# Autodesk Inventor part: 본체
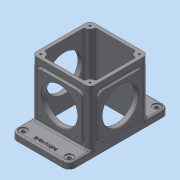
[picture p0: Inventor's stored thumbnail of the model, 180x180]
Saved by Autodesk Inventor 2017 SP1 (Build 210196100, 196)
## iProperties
Created: 2018-09
Part Number: 본체
Material: 알루미늄 6061
Document SubType Name: Modeling
Designer: mduedu
Density: 2.71 g/cm^3
Mass: 972.977 g
Surface Area: 957.184 cm^2
Volume: 359.032 cm^3
Appearance: 기본값
Author: mduedu
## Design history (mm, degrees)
sketch "스케치1"
  geometry: L1 (90, 52.5)-(-90, 52.5); L2 (-90, 52.5)-(-90, -52.5); L3 (-90, -52.5)-(90, -52.5); L4 (90, -52.5)-(90, 52.5); L5 (90, 52.5)-(-90, -52.5); L6 (-90, 52.5)-(90, -52.5); 1 further point
  constraints: 12 end point, 2 midpoint, 2 parallel, 1 horizontal, 1 perpendicular
  dimensions: "d0" = 180 distance of L3.end L2.end; "d1" = 105 distance of L2.end L1.end
extrude "돌출1" new body sketch "스케치1" distance "d2" = 12; taper "d3" = 0 deg
sketch "스케치2"
  geometry: L1 (-52.5, -52.5)-(52.5, -52.5); L2 (52.5, -52.5)-(52.5, 52.5); L3 (52.5, 52.5)-(-52.5, 52.5); L4 (-52.5, 52.5)-(-52.5, -52.5); L5 (-52.5, -52.5)-(52.5, 52.5); L6 (52.5, -52.5)-(-52.5, 52.5); 1 further point
  constraints: 12 end point, 2 midpoint, 2 parallel, 1 horizontal, 1 perpendicular
  dimensions: "d4" = 105 distance of L3.end L2.end; "d5" = 105 distance of L2.end L1.end
extrude "돌출2" join sketch "스케치2" distance "d6" = 100; taper "d7" = 0 deg
sketch "스케치14"
  geometry: L1 (-52.5, 52.5)-(52.5, 52.5) reference; L2 (52.5, 52.5)-(52.5, -52.5) reference; L3 (52.5, -52.5)-(-52.5, -52.5) reference; L4 (-52.5, -52.5)-(-52.5, 52.5) reference; L5 (46.5, 46.5)-(-46.5, 46.5); L6 (-46.5, 46.5)-(-46.5, -46.5); L7 (-46.5, -46.5)-(46.5, -46.5); L8 (46.5, -46.5)-(46.5, 46.5); 1 further point
  constraints: 8 end point, 3 other
  dimensions: "d85" = 6 distance between parallel lines of L5 L1
extrude "돌출10" cut sketch "스케치14" stored distance "d86" = 10; taper "d87" = 0 deg
fillet "모깎기1" dims "d12" = 8
sketch "스케치15"
  geometry: A1 r 8 centre (-44.5, 44.5) between (-44.5, 52.5) and (-52.5, 44.5) reference; A2 r 8 centre (44.5, 44.5) between (52.5, 44.5) and (44.5, 52.5) reference; A3 r 8 centre (44.5, -44.5) between (44.5, -52.5) and (52.5, -44.5) reference; A4 r 8 centre (-44.5, -44.5) between (-52.5, -44.5) and (-44.5, -52.5) reference; 5 further points
  constraints: 4 coincident, 4 vertical alignment, 8 other
extrude "돌출11" join sketch "스케치15" stored distance "d88" = 10; taper "d89" = 0 deg
fillet "모깎기15" dims "d90" = 3
sketch "스케치6"
  geometry: L1 (50, 19)-(130, 19); L2 (130, 19)-(130, 99); L3 (130, 99)-(50, 99); L4 (50, 99)-(50, 19); L5 (50, 19)-(130, 99); L6 (130, 19)-(50, 99); L7 (0, 0)-(180, 0) reference; 4 further points
  constraints: 12 end point, 4 midpoint, 2 parallel, 1 horizontal, 1 perpendicular, 1 vertical alignment
  dimensions: "d25" = 80 distance of L3.end L2.end; "d26" = 80 distance of L2.end L1.end; "d27" = 59 distance of point (90, 0) point (90, 59)
extrude "돌출6" join sketch "스케치6" distance "d28" = 3; taper "d29" = 0 deg
fillet "모깎기7" dims "d30" = 8
sketch "스케치7"
  geometry: C1 r 32.5 at (90, 59); 1 further point
  constraints: 1 centre point, 1 vertical alignment
  dimensions: "d32" = 65 diameter of C1; "d33" = 59 distance of C1.centre point (90, 0)
extrude "돌출7" cut sketch "스케치7" stored distance "d34" = 3; taper "d35" = 0 deg
fillet "모깎기9" dims "d36" = 3
sketch "스케치8"
  geometry: L1 (4.5, 7)-(84.5, 7); L2 (84.5, 7)-(84.5, 87); L3 (84.5, 87)-(4.5, 87); L4 (4.5, 87)-(4.5, 7); L5 (4.5, 7)-(84.5, 87); L6 (84.5, 7)-(4.5, 87); L7 (-8, -12)-(97, -12) reference; C1 r 32.5 at (44.5, 47); 4 further points
  constraints: 12 end point, 4 midpoint, 2 parallel, 1 centre point, 1 coincident, 1 horizontal, 1 perpendicular, 1 vertical alignment
  dimensions: "d37" = 80 distance of L3.end L2.end; "d38" = 80 distance of L2.end L1.end; "d39" = 59 distance from line of point (44.5, 47) L7; "d40" = 65 diameter of C1
extrude "돌출8" join sketch "스케치8" distance "d41" = 3; taper "d42" = 0 deg
fillet "모깎기10" dims "d43" = 8
extrude "돌출9" cut sketch "스케치8" stored distance "d44" = 3; taper "d45" = 0 deg
fillet "모깎기11" dims "d46" = 3
sketch "스케치9"
  geometry: L1 (50, 91)-(50, 27) reference; L2 (58, 19)-(122, 19) reference; L3 (130, 27)-(130, 91) reference; L4 (122, 99)-(58, 99) reference; C1 r 32.5 at (90, 59) reference; A1 r 8 centre (58, 91) between (58, 99) and (50, 91) reference; A2 r 8 centre (58, 27) between (50, 27) and (58, 19) reference; A3 r 8 centre (122, 27) between (122, 19) and (130, 27) reference; A4 r 8 centre (122, 91) between (130, 91) and (122, 99) reference; 5 further points
  constraints: 4 coincident
hole "구멍1" sketch "스케치9" at (58, 91), (122, 91), (122, 27), (58, 27) diameter "d47" = 3.242; stored, may be unused: countersink angle "d51" = 90 deg, drill point angle "d53" = 118 deg; dims "d48" = 6, "d49" = 4, "d50" = 2, "d52" = 9
sketch "스케치10"
  geometry: L1 (12.5, 7)-(76.5, 7) reference; L2 (84.5, 15)-(84.5, 79) reference; L3 (76.5, 87)-(12.5, 87) reference; L4 (4.5, 79)-(4.5, 15) reference; C1 r 32.5 at (44.5, 47) reference; A1 r 8 centre (12.5, 15) between (4.5, 15) and (12.5, 7) reference; A2 r 8 centre (76.5, 15) between (76.5, 7) and (84.5, 15) reference; A3 r 8 centre (76.5, 79) between (84.5, 79) and (76.5, 87) reference; A4 r 8 centre (12.5, 79) between (12.5, 87) and (4.5, 79) reference; 5 further points
  constraints: 4 coincident
hole "구멍2" sketch "스케치10" at (12.5, 79), (76.5, 79), (76.5, 15), (12.5, 15) diameter "d54" = 3.242; stored, may be unused: countersink angle "d58" = 90 deg, drill point angle "d60" = 118 deg; dims "d55" = 6, "d56" = 4, "d57" = 2, "d59" = 9
fillet "모깎기12" dims "d68" = 11
sketch "스케치16"
  geometry: A1 r 11 centre (-79, 41.5) between (-79, 52.5) and (-90, 41.5) reference; A2 r 11 centre (-79, -41.5) between (-90, -41.5) and (-79, -52.5) reference; A3 r 11 centre (79, 41.5) between (90, 41.5) and (79, 52.5) reference; A4 r 11 centre (79, -41.5) between (79, -52.5) and (90, -41.5) reference; 5 further points
  constraints: 4 coincident
hole "구멍5" sketch "스케치16" at (-79, 41.5), (79, 41.5), (79, -41.5), (-79, -41.5) diameter "d91" = 6.6; stored, may be unused: countersink angle "d95" = 90 deg, drill point angle "d97" = 118 deg; dims "d92" = 6, "d93" = 14, "d94" = 2, "d96" = 8
fillet "모깎기13" dims "d77" = 3
fillet "모깎기14" dims "d78" = 3
chamfer "모따기1" distance "d79" = 1; stored, may be unused: second distance "d80" = 2, angle "d81" = 45 deg
sketch "스케치17"
  geometry: A1 r 8 centre (-44.5, 44.5) between (-44.5, 52.5) and (-52.5, 44.5) reference; A2 r 8 centre (-44.5, -44.5) between (-52.5, -44.5) and (-44.5, -52.5) reference; A3 r 8 centre (44.5, -44.5) between (44.5, -52.5) and (52.5, -44.5) reference; A4 r 8 centre (44.5, 44.5) between (52.5, 44.5) and (44.5, 52.5) reference; 5 further points
  constraints: 4 coincident
hole "구멍6" sketch "스케치17" at (-44.5, 44.5), (44.5, 44.5), (44.5, -44.5), (-44.5, -44.5) diameter "d98" = 3.242; stored, may be unused: countersink angle "d102" = 90 deg, drill point angle "d104" = 118 deg; dims "d99" = 8, "d100" = 15, "d101" = 2, "d103" = 10
sketch "스케치13"
  geometry: L1 (90, -41.5)-(90, 41.5) reference; 2 further points
  constraints: 1 horizontal alignment, 1 other
  dimensions: "d82" = 10 distance from line of point (80, 0) L1
feature "엠보싱1" sketch "스케치13" dims "d0" = 180, "d1" = 105, "d25" = 80, "d26" = 80, "d27" = 59, "d83" = 0.5, "d84" = 0
node "솔리드1"
mirror "대칭1"
mirror "대칭2"
node "투영된 루프2"
node "투영된 루프3"
node "투영된 루프6"
